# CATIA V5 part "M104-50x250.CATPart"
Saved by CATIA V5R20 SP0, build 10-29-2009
Part number: M104-50x250
Source: Unknown
Bounding box of the stored display mesh (mm): x -24.865 to 24.865, y -24.997 to 24.997, z 0 to 250
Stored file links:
  C:\Users\Utente\Desktop\IO LAVORO\3D X SITO CF\X SITO\M104\M104-50x250.CATPart
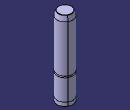
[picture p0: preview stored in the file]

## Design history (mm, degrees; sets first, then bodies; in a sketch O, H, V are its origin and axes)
Body1 (main body)
  Solid1 "PartBody": solid without history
